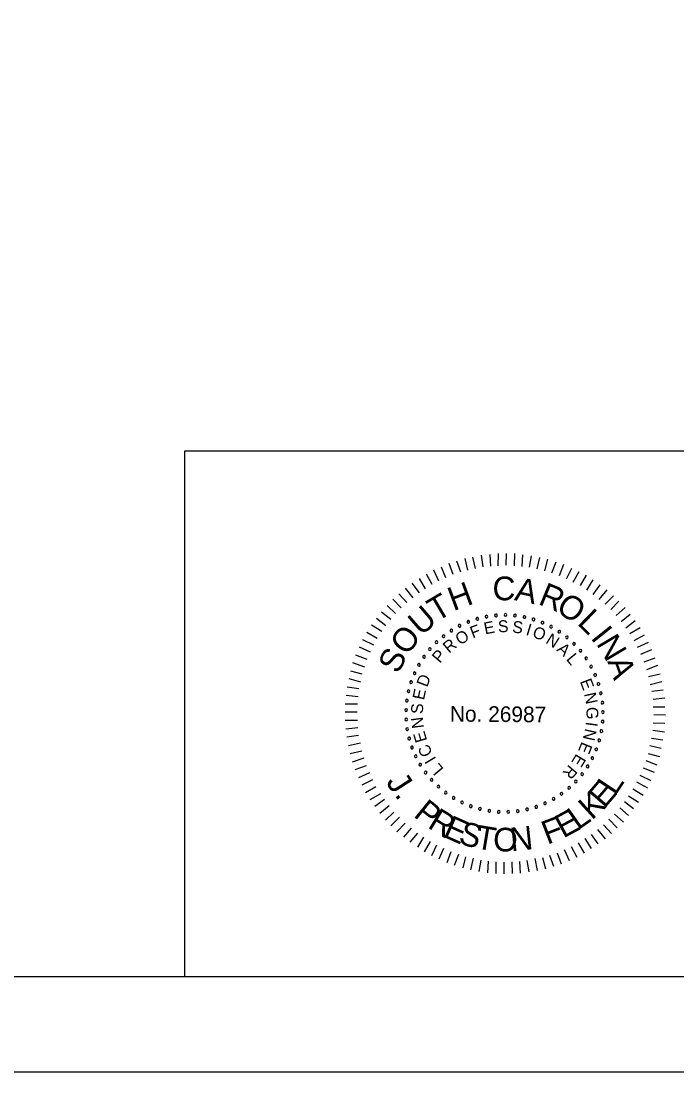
# Model space of a CAD drawing. Extents: x 1970675.2 to 1970711.3, y 796145.2 to 796167.2.
# Drawn here: x 1970697.01 to 1970700.45, y 796145.25 to 796150.75 of the extents above; entities that cross this region are included whole.
import ezdxf

# ---------------------------------------------------------------- set-up
doc = ezdxf.new("R2010")
doc.units = 0
for name, color, linetype in [('BR_BORDER LINES', 7, 'Continuous'), ('BR_TEXT', 7, 'Continuous'), ('Level 31', 7, 'Continuous')]:
    doc.layers.add(name, color=color, linetype=linetype)

msp = doc.modelspace()

# ---------------------------------------------------------------- linework, layer by layer
at = {"layer": 'BR_BORDER LINES'}
for p, q in [((1970697.8703, 796148.4964), (1970703.2355, 796148.4964)), ((1970697.8703, 796145.7463), (1970697.8703, 796148.4964)), ((1970677.0698, 796145.7463), (1970710.7358, 796145.7463))]:
    msp.add_line(p, q, dxfattribs=at)
at = {"layer": 'BR_TEXT'}
for p, q in [((1970699.432, 796147.8895), (1970699.4231, 796147.9504)), ((1970699.4715, 796147.8934), (1970699.4677, 796147.9544)), ((1970699.511, 796147.8957), (1970699.5116, 796147.96)), ((1970699.5531, 796147.8979), (1970699.5536, 796147.9597)), ((1970699.5951, 796147.895), (1970699.5974, 796147.9593)), ((1970699.6354, 796147.8921), (1970699.6402, 796147.9529)), ((1970699.674, 796147.8875), (1970699.6848, 796147.9483)), ((1970699.2755, 796147.8495), (1970699.2545, 796147.9081)), ((1970699.3151, 796147.8621), (1970699.2932, 796147.9198)), ((1970699.3512, 796147.8721), (1970699.338, 796147.9331)), ((1970699.3925, 796147.882), (1970699.3784, 796147.9414)), ((1970699.7143, 796147.8794), (1970699.7285, 796147.9385)), ((1970699.7554, 796147.8688), (1970699.7713, 796147.9295)), ((1970699.7922, 796147.8582), (1970699.8141, 796147.9155)), ((1970699.8316, 796147.8449), (1970699.8535, 796147.9031)), ((1970699.1652, 796147.7981), (1970699.1348, 796147.8524)), ((1970699.1997, 796147.8158), (1970699.1735, 796147.8718)), ((1970699.2368, 796147.8327), (1970699.2132, 796147.8887)), ((1970699.8675, 796147.8275), (1970699.8954, 796147.883)), ((1970699.9034, 796147.81), (1970699.9347, 796147.8656)), ((1970699.941, 796147.7917), (1970699.9732, 796147.8455)), ((1970699.0988, 796147.7532), (1970699.0597, 796147.8041)), ((1970699.1299, 796147.7744), (1970699.0994, 796147.8287)), ((1970699.9743, 796147.7674), (1970700.0082, 796147.8212)), ((1970700.0075, 796147.7457), (1970700.044, 796147.796)), ((1970699.0323, 796147.7031), (1970698.9906, 796147.748)), ((1970699.0651, 796147.7277), (1970699.0252, 796147.7778)), ((1970700.0399, 796147.7197), (1970700.0806, 796147.7691)), ((1970700.0715, 796147.6945), (1970700.1147, 796147.7388)), ((1970698.9735, 796147.6452), (1970698.93, 796147.6876)), ((1970699.0029, 796147.6759), (1970698.9586, 796147.72)), ((1970700.0995, 796147.6668), (1970700.1428, 796147.7102)), ((1970700.1276, 796147.6357), (1970700.1752, 796147.6774)), ((1970698.9223, 796147.5804), (1970698.8728, 796147.6203)), ((1970698.9483, 796147.6137), (1970698.8988, 796147.6527)), ((1970700.1548, 796147.6037), (1970700.2015, 796147.6419)), ((1970698.9006, 796147.5514), (1970698.8468, 796147.5845)), ((1970700.1786, 796147.57), (1970700.2278, 796147.6091)), ((1970700.2006, 796147.5407), (1970700.2532, 796147.5729)), ((1970698.8588, 796147.4805), (1970698.8024, 796147.5085)), ((1970698.8762, 796147.5147), (1970698.8225, 796147.5469)), ((1970700.2226, 796147.5036), (1970700.2761, 796147.5349)), ((1970698.8413, 796147.4438), (1970698.7841, 796147.4692)), ((1970700.2404, 796147.4691), (1970700.2981, 796147.4961)), ((1970700.2581, 796147.4321), (1970700.315, 796147.4565)), ((1970698.8238, 796147.4053), (1970698.7657, 796147.4272)), ((1970700.2749, 796147.3933), (1970700.3318, 796147.4143)), ((1970698.7992, 796147.3291), (1970698.7384, 796147.3442)), ((1970698.8115, 796147.3651), (1970698.7499, 796147.3879)), ((1970700.2883, 796147.3529), (1970700.346, 796147.3747)), ((1970698.792, 796147.2871), (1970698.7295, 796147.3031)), ((1970700.2984, 796147.3168), (1970700.3585, 796147.3308)), ((1970700.3066, 796147.2746), (1970700.3668, 796147.2896)), ((1970698.7814, 796147.2512), (1970698.7205, 796147.2594)), ((1970700.3149, 796147.2385), (1970700.3741, 796147.2458)), ((1970698.7768, 796147.21), (1970698.715, 796147.2174)), ((1970700.3214, 796147.1973), (1970700.3824, 796147.2036)), ((1970698.7718, 796147.1294), (1970698.7092, 796147.1299)), ((1970698.7738, 796147.1706), (1970698.7095, 796147.1711)), ((1970700.3228, 796147.1578), (1970700.3829, 796147.1573)), ((1970698.7732, 796147.0865), (1970698.7088, 796147.0853)), ((1970700.3221, 796147.0737), (1970700.3822, 796147.0715)), ((1970700.325, 796147.1166), (1970700.3859, 796147.1161)), ((1970698.7754, 796147.0478), (1970698.7136, 796147.0406)), ((1970700.32, 796147.0351), (1970700.3809, 796147.0269)), ((1970698.7794, 796147.0066), (1970698.7183, 796146.9977)), ((1970698.7893, 796146.9671), (1970698.7266, 796146.9539)), ((1970700.3129, 796146.994), (1970700.372, 796146.984)), ((1970698.7959, 796146.9249), (1970698.7348, 796146.9109)), ((1970700.295, 796146.9126), (1970700.3549, 796146.8975)), ((1970700.3039, 796146.9546), (1970700.3639, 796146.9403)), ((1970698.8076, 796146.888), (1970698.7456, 796146.867)), ((1970698.8192, 796146.8493), (1970698.7607, 796146.8283)), ((1970700.2844, 796146.8758), (1970700.3417, 796146.8538)), ((1970698.8361, 796146.8122), (1970698.7784, 796146.7852)), ((1970700.2529, 796146.8005), (1970700.3093, 796146.7726)), ((1970700.2704, 796146.8373), (1970700.3268, 796146.8153)), ((1970698.853, 796146.776), (1970698.7961, 796146.7465)), ((1970698.8698, 796146.739), (1970698.8155, 796146.7077)), ((1970700.2346, 796146.7646), (1970700.2918, 796146.7341)), ((1970698.8936, 796146.7019), (1970698.8392, 796146.6706)), ((1970700.1936, 796146.6911), (1970700.2457, 796146.659)), ((1970700.2162, 796146.7279), (1970700.2692, 796146.6957)), ((1970698.9148, 796146.6725), (1970698.8647, 796146.636)), ((1970698.9402, 796146.6388), (1970698.8901, 796146.5998)), ((1970700.1468, 796146.6289), (1970700.1928, 796146.589)), ((1970700.1711, 796146.6622), (1970700.2197, 796146.6248)), ((1970698.9649, 796146.6052), (1970698.9207, 796146.5643)), ((1970698.9938, 796146.5792), (1970698.9488, 796146.5341)), ((1970700.119, 796146.5956), (1970700.1659, 796146.5541)), ((1970699.0227, 796146.5489), (1970698.9803, 796146.5029)), ((1970699.0552, 796146.5229), (1970699.0144, 796146.476)), ((1970700.0619, 796146.5403), (1970700.1044, 796146.4936)), ((1970700.0905, 796146.5701), (1970700.133, 796146.5243)), ((1970699.0884, 796146.4969), (1970699.0485, 796146.4492)), ((1970699.1191, 796146.4752), (1970699.0878, 796146.4231)), ((1970699.9635, 796146.4682), (1970699.9966, 796146.4156)), ((1970699.9972, 796146.4894), (1970700.0328, 796146.441)), ((1970700.03, 796146.5149), (1970700.0699, 796146.4673)), ((1970699.1541, 796146.4526), (1970699.1228, 796146.3988)), ((1970699.1883, 796146.4326), (1970699.1612, 796146.377)), ((1970699.225, 796146.4151), (1970699.2005, 796146.3595)), ((1970699.8558, 796146.4099), (1970699.8827, 796146.3539)), ((1970699.8919, 796146.4267), (1970699.9224, 796146.3707)), ((1970699.9299, 796146.4462), (1970699.9612, 796146.3918)), ((1970699.2635, 796146.3976), (1970699.2416, 796146.3411)), ((1970699.3029, 796146.3853), (1970699.2801, 796146.3271)), ((1970699.3388, 796146.3729), (1970699.3246, 796146.3139)), ((1970699.38, 796146.3658), (1970699.3648, 796146.3041)), ((1970699.4193, 796146.3543), (1970699.4094, 796146.296)), ((1970699.6613, 796146.3523), (1970699.6712, 796146.2938)), ((1970699.7018, 796146.3631), (1970699.715, 796146.3012)), ((1970699.743, 796146.3696), (1970699.758, 796146.3103)), ((1970699.78, 796146.3813), (1970699.801, 796146.3228)), ((1970699.8196, 796146.393), (1970699.8406, 796146.3362)), ((1970699.4588, 796146.3497), (1970699.454, 796146.2879)), ((1970699.4982, 796146.3468), (1970699.4977, 796146.285)), ((1970699.5402, 796146.3438), (1970699.5397, 796146.2829)), ((1970699.5823, 796146.3461), (1970699.5835, 796146.2842)), ((1970699.6227, 796146.3483), (1970699.6264, 796146.2865))]:
    msp.add_line(p, q, dxfattribs=at)
for centre, start, end in [((1970699.4011, 796147.6179), 16.1422, 196.1422), ((1970699.4011, 796147.6179), 196.1422, 16.1422), ((1970699.4496, 796147.6294), 10.6038, 190.6038), ((1970699.4496, 796147.6294), 190.6038, 10.6038), ((1970699.499, 796147.6361), 5.0653, 185.0653), ((1970699.499, 796147.6361), 185.0653, 5.0653), ((1970699.5488, 796147.638), 359.5268, 179.5268), ((1970699.5488, 796147.638), 179.5268, 359.5268), ((1970699.5985, 796147.635), 173.9884, 353.9884), ((1970699.5985, 796147.635), 353.9884, 173.9884), ((1970699.6478, 796147.6273), 168.4499, 348.4499), ((1970699.6478, 796147.6273), 348.4499, 168.4499), ((1970699.696, 796147.6149), 162.9114, 342.9114), ((1970699.696, 796147.6149), 342.9114, 162.9114), ((1970699.2653, 796147.5565), 32.7576, 212.7576), ((1970699.3085, 796147.5813), 27.2191, 207.2191), ((1970699.3085, 796147.5813), 207.2191, 27.2191), ((1970699.3539, 796147.6019), 21.6807, 201.6807), ((1970699.3539, 796147.6019), 201.6807, 21.6807), ((1970699.7429, 796147.5979), 157.373, 337.373), ((1970699.7429, 796147.5979), 337.373, 157.373), ((1970699.7878, 796147.5764), 151.8345, 331.8345), ((1970699.7878, 796147.5764), 331.8345, 151.8345), ((1970699.2247, 796147.5276), 38.2961, 218.2961), ((1970699.2247, 796147.5276), 218.2961, 38.2961), ((1970699.2653, 796147.5565), 212.7576, 32.7576), ((1970699.8305, 796147.5507), 146.2961, 326.2961), ((1970699.8305, 796147.5507), 326.2961, 146.2961), ((1970699.8705, 796147.521), 140.7576, 320.7576), ((1970699.8705, 796147.521), 320.7576, 140.7576), ((1970699.1528, 796147.4588), 49.373, 229.373), ((1970699.1528, 796147.4588), 229.373, 49.373), ((1970699.1871, 796147.495), 43.8345, 223.8345), ((1970699.1871, 796147.495), 223.8345, 43.8345), ((1970699.9075, 796147.4876), 135.2191, 315.2191), ((1970699.9075, 796147.4876), 315.2191, 135.2191), ((1970699.9411, 796147.4508), 129.6807, 309.6807), ((1970699.9411, 796147.4508), 309.6807, 129.6807), ((1970699.1221, 796147.4196), 54.9114, 234.9114), ((1970699.1221, 796147.4196), 234.9114, 54.9114), ((1970699.9709, 796147.4109), 124.1422, 304.1422), ((1970699.9709, 796147.4109), 304.1422, 124.1422), ((1970699.0954, 796147.3775), 60.4499, 240.4499), ((1970699.0954, 796147.3775), 240.4499, 60.4499), ((1970699.9968, 796147.3683), 118.6038, 298.6038), ((1970699.9968, 796147.3683), 298.6038, 118.6038), ((1970699.0547, 796147.2867), 71.5268, 251.5268), ((1970699.0547, 796147.2867), 251.5268, 71.5268), ((1970699.0729, 796147.3331), 65.9884, 245.9884), ((1970699.0729, 796147.3331), 245.9884, 65.9884), ((1970700.0184, 796147.3234), 113.0653, 293.0653), ((1970700.0184, 796147.3234), 293.0653, 113.0653), ((1970699.0411, 796147.2387), 77.0653, 257.0653), ((1970699.0411, 796147.2387), 257.0653, 77.0653), ((1970700.0356, 796147.2766), 107.5268, 287.5268), ((1970700.0356, 796147.2766), 287.5268, 107.5268), ((1970700.0482, 796147.2284), 101.9884, 281.9884), ((1970700.0482, 796147.2284), 281.9884, 101.9884), ((1970699.0322, 796147.1897), 82.6038, 262.6038), ((1970699.0322, 796147.1897), 262.6038, 82.6038), ((1970700.0561, 796147.1792), 96.4499, 276.4499), ((1970700.0561, 796147.1792), 276.4499, 96.4499), ((1970699.0281, 796147.14), 88.1422, 268.1422), ((1970699.0281, 796147.14), 268.1422, 88.1422), ((1970700.0592, 796147.1295), 90.9114, 270.9114), ((1970700.0592, 796147.1295), 270.9114, 90.9114), ((1970699.0288, 796147.0902), 93.6807, 273.6807), ((1970699.0288, 796147.0902), 273.6807, 93.6807), ((1970700.0575, 796147.0797), 85.373, 265.373), ((1970700.0575, 796147.0797), 265.373, 85.373), ((1970699.0343, 796147.0407), 99.2191, 279.2191), ((1970699.0343, 796147.0407), 279.2191, 99.2191), ((1970700.0509, 796147.0303), 79.8345, 259.8345), ((1970700.0509, 796147.0303), 259.8345, 79.8345), ((1970699.0446, 796146.9919), 104.7576, 284.7576), ((1970699.0446, 796146.9919), 284.7576, 104.7576), ((1970700.0397, 796146.9817), 74.2961, 254.2961), ((1970700.0397, 796146.9817), 254.2961, 74.2961), ((1970699.0595, 796146.9444), 110.2961, 290.2961), ((1970699.0595, 796146.9444), 290.2961, 110.2961), ((1970699.0789, 796146.8985), 115.8345, 295.8345), ((1970699.0789, 796146.8985), 295.8345, 115.8345), ((1970700.0238, 796146.9345), 68.7576, 248.7576), ((1970700.0238, 796146.9345), 248.7576, 68.7576), ((1970699.1027, 796146.8547), 121.373, 301.373), ((1970699.1027, 796146.8547), 301.373, 121.373), ((1970699.9788, 796146.8457), 57.6807, 237.6807), ((1970699.9788, 796146.8457), 237.6807, 57.6807), ((1970700.0034, 796146.889), 63.2191, 243.2191), ((1970700.0034, 796146.889), 243.2191, 63.2191), ((1970699.1306, 796146.8134), 126.9114, 306.9114), ((1970699.1306, 796146.8134), 306.9114, 126.9114), ((1970699.9501, 796146.805), 52.1422, 232.1422), ((1970699.9501, 796146.805), 232.1422, 52.1422), ((1970699.1623, 796146.775), 132.4499, 312.4499), ((1970699.1623, 796146.775), 312.4499, 132.4499), ((1970699.1976, 796146.7398), 137.9884, 317.9884), ((1970699.1976, 796146.7398), 317.9884, 137.9884), ((1970699.8815, 796146.7328), 41.0653, 221.0653), ((1970699.8815, 796146.7328), 221.0653, 41.0653), ((1970699.9175, 796146.7672), 46.6038, 226.6038), ((1970699.9175, 796146.7672), 226.6038, 46.6038), ((1970699.2361, 796146.7082), 143.5268, 323.5268), ((1970699.2361, 796146.7082), 323.5268, 143.5268), ((1970699.2775, 796146.6805), 149.0653, 329.0653), ((1970699.2775, 796146.6805), 329.0653, 149.0653), ((1970699.8004, 796146.6751), 29.9884, 209.9884), ((1970699.8423, 796146.702), 35.5268, 215.5268), ((1970699.8423, 796146.702), 215.5268, 35.5268), ((1970699.3214, 796146.6569), 154.6038, 334.6038), ((1970699.3214, 796146.6569), 334.6038, 154.6038), ((1970699.3674, 796146.6376), 160.1422, 340.1422), ((1970699.3674, 796146.6376), 340.1422, 160.1422), ((1970699.415, 796146.6229), 345.6807, 165.6807), ((1970699.6618, 796146.6203), 13.373, 193.373), ((1970699.7097, 796146.6341), 18.9114, 198.9114), ((1970699.7097, 796146.6341), 198.9114, 18.9114), ((1970699.756, 796146.6524), 24.4499, 204.4499), ((1970699.756, 796146.6524), 204.4499, 24.4499), ((1970699.8004, 796146.6751), 209.9884, 29.9884), ((1970699.415, 796146.6229), 165.6807, 345.6807), ((1970699.4638, 796146.6128), 351.2191, 171.2191), ((1970699.4638, 796146.6128), 171.2191, 351.2191), ((1970699.5133, 796146.6075), 356.7576, 176.7576), ((1970699.5133, 796146.6075), 176.7576, 356.7576), ((1970699.5632, 796146.607), 2.2961, 182.2961), ((1970699.5632, 796146.607), 182.2961, 2.2961), ((1970699.6128, 796146.6113), 7.8345, 187.8345), ((1970699.6128, 796146.6113), 187.8345, 7.8345), ((1970699.6618, 796146.6203), 193.373, 13.373)]:
    msp.add_arc(centre, 0.00701, start, end, dxfattribs=at)
at = {"layer": 'Level 31'}
msp.add_lwpolyline([(1970675.2365, 796145.2464), (1970711.2364, 796145.2464), (1970711.2364, 796167.2463), (1970675.2365, 796167.2463)], close=True, dxfattribs=at)

# ---------------------------------------------------------------- texts
at = {"layer": 'BR_TEXT'}
for s, height, rotation, p in [('C', 0.1241, 359.5482, (1970699.4803, 796147.7155)), ('H', 0.1241, 20.3637, (1970699.2759, 796147.6572)), ('A', 0.1241, 348.1981, (1970699.5917, 796147.7163)), ('R', 0.1241, 337.4344, (1970699.715, 796147.6965)), ('T', 0.1241, 30.4992, (1970699.188, 796147.5997)), ('O', 0.1239, 326.5869, (1970699.8072, 796147.6597)), ('U', 0.1241, 40.8022, (1970699.1068, 796147.525)), ('L', 0.1241, 315.9488, (1970699.9198, 796147.5919)), ('O', 0.1241, 52.0267, (1970699.0323, 796147.421)), ('F', 0.0622, 20.6127, (1970699.3772, 796147.5143)), ('E', 0.0622, 11.4103, (1970699.4423, 796147.536)), ('S', 0.0622, 2.208, (1970699.5102, 796147.547)), ('S', 0.0622, 352.6608, (1970699.5814, 796147.5468)), ('I', 0.0622, 343.1136, (1970699.6517, 796147.5348)), ('O', 0.0622, 338.4392, (1970699.6851, 796147.5247)), ('I', 0.1241, 308.6613, (1970699.9912, 796147.5176)), ('R', 0.0622, 40.3949, (1970699.2537, 796147.4344)), ('O', 0.0622, 30.8477, (1970699.3098, 796147.4783)), ('N', 0.0622, 328.2042, (1970699.7547, 796147.4933)), ('N', 0.1241, 300.7037, (1970700.0218, 796147.4883)), ('S', 0.1239, 63.2511, (1970698.9869, 796147.3254)), ('P', 0.0622, 49.9421, (1970699.2056, 796147.3818)), ('A', 0.0622, 318.657, (1970699.8137, 796147.4532)), ('L', 0.0622, 309.4546, (1970699.8635, 796147.4059)), ('A', 0.1241, 289.4792, (1970700.081, 796147.3952)), ('D', 0.0622, 69.0364, (1970699.1386, 796147.2566)), ('E', 0.0622, 291.049, (1970699.9373, 796147.2906)), ('E', 0.0622, 78.2388, (1970699.122, 796147.1899)), ('N', 0.0622, 281.8466, (1970699.9595, 796147.2256)), ('S', 0.0622, 87.786, (1970699.1163, 796147.1189)), ('No. 26987', 0.08175, 359.5268, (1970699.2574, 796147.0804)), ('G', 0.0622, 272.2995, (1970699.9713, 796147.1553)), ('N', 0.0622, 97.3332, (1970699.1225, 796147.0479)), ('I', 0.0622, 262.4084, (1970699.9709, 796147.0814)), ('E', 0.0622, 106.5355, (1970699.1395, 796146.9813)), ('N', 0.0622, 257.7339, (1970699.9664, 796147.0468)), ('C', 0.0622, 116.4266, (1970699.1694, 796146.9138)), ('E', 0.0622, 248.1867, (1970699.9483, 796146.9779)), ('E', 0.0622, 238.9844, (1970699.9204, 796146.9151)), ('I', 0.0622, 121.1011, (1970699.1875, 796146.8839)), ('L', 0.0622, 129.9595, (1970699.2281, 796146.8318)), ('R', 0.0622, 229.782, (1970699.8827, 796146.8577)), ('J', 0.1236, 302.9559, (1970698.9202, 796146.7633)), ('E', 0.1236, 49.3639, (1970700.0662, 796146.6214)), ('L', 0.1236, 56.4247, (1970700.1237, 796146.6891)), ('.', 0.1236, 309.3974, (1970698.9643, 796146.6953)), ('K', 0.1236, 42.3031, (1970700.0009, 796146.5613)), ('P', 0.1236, 321.1035, (1970699.0627, 796146.5861)), ('L', 0.1236, 35.2422, (1970699.9286, 796146.5097)), ('R', 0.1236, 328.5359, (1970699.136, 796146.528)), ('E', 0.1236, 335.9684, (1970699.2161, 796146.4799)), ('F', 0.1236, 21.1206, (1970699.7679, 796146.4348)), ('E', 0.1236, 28.1814, (1970699.8506, 796146.4673)), ('S', 0.1236, 343.0292, (1970699.2974, 796146.4442)), ('T', 0.1236, 350.4617, (1970699.3871, 796146.4177)), ('O', 0.1236, 358.1419, (1970699.4825, 796146.4028)), ('N', 0.1236, 5.8221, (1970699.579, 796146.4007))]:
    msp.add_text(s, height=height, rotation=rotation, dxfattribs=at).set_placement(p)

doc.saveas('drawing.dxf')
